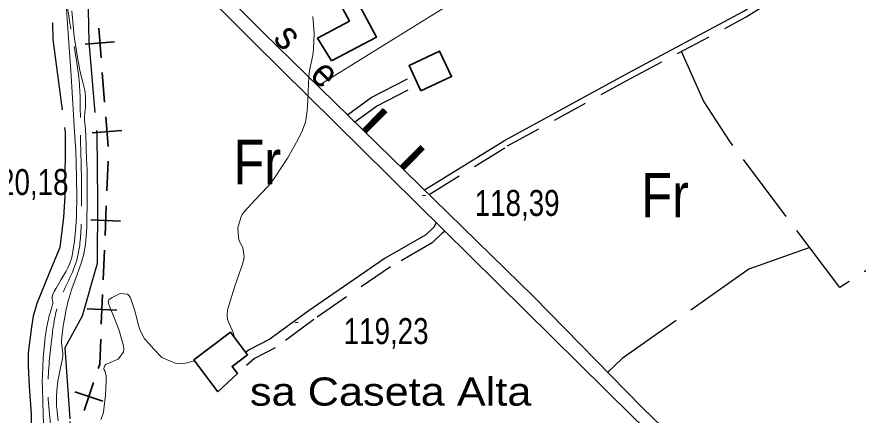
# Model space of a CAD drawing. Extents: x 483855 to 488461, y 4388206 to 4391419.
# Drawn here: x 486490 to 486774, y 4389689.8 to 4389824.2 of the extents above; entities that cross this region are included whole.
import ezdxf
from ezdxf.enums import TextEntityAlignment as Align

# ---------------------------------------------------------------- set-up
doc = ezdxf.new("R2010")
doc.units = 0
doc.header["$LTSCALE"] = 4
doc.linetypes.add('LONG_DASHED', pattern=[7.5, 6, -1.5])
doc.linetypes.add('MEDIUM_DASHED', pattern=[4.5, 3, -1.5])
for name, color, linetype, lineweight in [('15', 7, 'LONG_DASHED', 13), ('25', 7, 'LONG_DASHED', 25), ('34', 7, 'Continuous', 35), ('36', 7, 'Continuous', 25), ('38', 7, 'Continuous', 25), ('47', 7, 'Continuous', 35), ('51', 7, 'Continuous', 13), ('7', 7, 'Continuous', 13), ('9', 7, 'Continuous', 13)]:
    doc.layers.add(name, color=color, linetype=linetype, lineweight=lineweight)
doc.layers.add('31', color=7, linetype='Continuous')
doc.layers.add('5', color=7, linetype='Continuous')

msp = doc.modelspace()

# ---------------------------------------------------------------- linework, layer by layer
at = {"layer": '15'}
msp.add_spline([(486492.68, 4389960.44), (486491.95, 4389948.36), (486491.53, 4389930.05), (486491.32, 4389921.58), (486491.04, 4389911.75), (486494.3, 4389888.5), (486502.5, 4389873.13), (486507.25, 4389860.99), (486507.49, 4389847.04), (486507.43, 4389840.29), (486506.92, 4389834.21), (486508.29, 4389820.18), (486511.17, 4389801.36), (486511.49, 4389786.96), (486511.82, 4389771.21), (486511.77, 4389754.33), (486510.14, 4389741.8), (486504.02, 4389727.16), (486501.64, 4389714.03), (486500.54, 4389697.67), (486502.15, 4389678.02), (486502.16, 4389668.5), (486502.11, 4389652.44), (486501.97, 4389650.72), (486502.65, 4389644.87), (486508.82, 4389631.83), (486513.8, 4389616.98), (486525.15, 4389604.4), (486535.89, 4389591.74), (486545.82, 4389574.65), (486550.2, 4389561), (486556.75, 4389546.91), (486564.34, 4389534.32), (486574.03, 4389528.64), (486583.64, 4389523.1), (486593.92, 4389522.44), (486595.43, 4389514.79), (486597.62, 4389507.3), (486600.4, 4389500.4)], degree=3, dxfattribs=at)
at = {"layer": '25'}
for points in [[(486497.71, 4389931.68), (486497.94, 4389909.51), (486508.42, 4389877.57), (486513.1, 4389859.2), (486514.85, 4389845.55), (486514.71, 4389840.15), (486514.13, 4389826.5), (486514.3, 4389815.77), (486517.05, 4389784.57), (486517.31, 4389761.99), (486517.12, 4389740.98), (486512.05, 4389723.2), (486506.21, 4389712.54), (486507.98, 4389687.63), (486507.1, 4389672.93), (486507.66, 4389654.55), (486513.4, 4389633.26), (486522.35, 4389616.92), (486540.46, 4389597.52), (486552.42, 4389577.36), (486559.36, 4389554.57)], [(486922.38, 4389931.06), (486935.95, 4389908.14), (486948.56, 4389882.68), (486960.66, 4389857.75), (486892.81, 4389816.46), (486846.7, 4389783.53), (486767.8, 4389732.92), (486730.53, 4389782.29)], [(486501.94, 4389852.2), (486502.14, 4389816.57), (486506.4, 4389785.22), (486506.28, 4389763.7), (486505.84, 4389756.64), (486504.58, 4389746.36), (486500.92, 4389737.66), (486496.74, 4389727.52), (486495.55, 4389723.17), (486494.95, 4389719.64), (486493.92, 4389710.79), (486493.92, 4389706.51), (486494.23, 4389699.54), (486494.92, 4389690.24), (486495.01, 4389681.61)], [(486730.53, 4389782.29), (486721.8, 4389795.87), (486714.34, 4389812.5)], [(486757.69, 4389746.32), (486737.12, 4389739.05), (486694.32, 4389708.95), (486689.54, 4389704.28)]]:
    msp.add_lwpolyline(points, dxfattribs=at)
at = {"layer": '34'}
for p, q in [((486518.47, 4389810.34), (486517.67, 4389820.31)), ((486523.05, 4389815.73), (486513.09, 4389814.92)), ((486519.68, 4389795.39), (486518.87, 4389805.36)), ((486520.88, 4389780.44), (486520.08, 4389790.4)), ((486525.47, 4389785.82), (486515.5, 4389785.02)), ((486520.44, 4389765.45), (486520.85, 4389775.44)), ((486519.81, 4389750.47), (486520.23, 4389760.46)), ((486525.01, 4389755.25), (486515.02, 4389755.67)), ((486519.19, 4389735.48), (486519.6, 4389745.47)), ((486518.56, 4389720.49), (486518.98, 4389730.48)), ((486523.77, 4389725.28), (486513.77, 4389725.7)), ((486512.78, 4389691.35), (486515.95, 4389700.84)), ((486519.11, 4389694.51), (486509.62, 4389697.68))]:
    msp.add_line(p, q, dxfattribs=at)
msp.add_lwpolyline([(486517.53, 4389705.58), (486518, 4389707), (486518.35, 4389715.5)], dxfattribs=at)
at = {"layer": '36'}
for points in [[(486573.3, 4389818.73), (486553.3, 4389838.83)], [(486550.35, 4389835.26), (486570.03, 4389815.48)], [(486573.3, 4389818.73), (486664.59, 4389729.76), (486701.09, 4389692.46), (486732.39, 4389662.19), (486764.81, 4389627.09), (486793.34, 4389595.58), (486828.71, 4389556.83), (486860.49, 4389521.58), (486879.69, 4389504.55), (486889.19, 4389496.62), (486900.68, 4389489.84), (486913.43, 4389477.11), (486933.6, 4389456.96), (486953.64, 4389433.43), (486986.75, 4389395.23)], [(486570.03, 4389815.48), (486697.95, 4389689.3), (486729.21, 4389659.07), (486761.53, 4389624.08), (486790.05, 4389592.58), (486825.42, 4389553.84), (486857.35, 4389518.41), (486876.78, 4389501.18), (486886.62, 4389492.97), (486897.93, 4389486.3), (486910.28, 4389473.96), (486930.33, 4389453.93), (486950.27, 4389430.53), (486983.41, 4389392.29)]]:
    msp.add_lwpolyline(points, dxfattribs=at)
at = {"layer": '38'}
for points in [[(486627.64, 4389765.77), (486654.64, 4389782.42), (486696.21, 4389805.2), (486735.15, 4389825.93), (486757.25, 4389839.95), (486767.23, 4389839.31), (486769.19, 4389838.81)], [(486601.64, 4389791.11), (486609.69, 4389796.95), (486621.94, 4389803.22)], [(486631.53, 4389754.71), (486630.82, 4389753.25), (486628.1, 4389750.66), (486614.39, 4389742.77), (486588.33, 4389724.92), (486575.48, 4389715.42), (486568.26, 4389711.79), (486567.34, 4389710.97)]]:
    msp.add_lwpolyline(points, dxfattribs=at)
at = {"layer": '38', "linetype": 'MEDIUM_DASHED'}
for points in [[(486629.17, 4389764.28), (486655.69, 4389780.63), (486697.19, 4389803.37), (486736.2, 4389824.14), (486757.8, 4389837.83), (486766.91, 4389837.25), (486768.67, 4389836.8)], [(486604.11, 4389788.7), (486611.48, 4389794.04), (486623.49, 4389800.19)], [(486634.46, 4389751.78), (486633.63, 4389751.19), (486630.17, 4389747.9), (486616.21, 4389739.87), (486590.32, 4389722.13), (486577.28, 4389712.49), (486570.21, 4389708.94), (486567.56, 4389706.55)]]:
    msp.add_lwpolyline(points, dxfattribs=at)
at = {"layer": '47'}
for points in [[(486596.25, 4389809.28), (486611.39, 4389817.29), (486604.93, 4389829.48), (486600.07, 4389826.91), (486602.31, 4389822.67), (486591.5, 4389816.96)], [(486626.45, 4389799.19), (486622.43, 4389807.79), (486632.73, 4389812.6), (486636.75, 4389804)], [(486557.92, 4389697.74), (486549.8, 4389708.46), (486562.15, 4389717.83), (486567.92, 4389710.22), (486562.71, 4389706.28), (486564.51, 4389703.89)]]:
    msp.add_lwpolyline(points, close=True, dxfattribs=at)
at = {"layer": '51'}
msp.add_lwpolyline([(486587.29, 4389889.23), (486602.95, 4389861.48), (486638.81, 4389830.08), (486592.6, 4389801.5)], dxfattribs=at)
at = {"layer": '7'}
for p, q in [((486626.98, 4389763.9), (486627.98, 4389763.9)), ((486583.99, 4389721.05), (486584.99, 4389721.05))]:
    msp.add_line(p, q, dxfattribs=at)
at = {"layer": '9'}
msp.add_line((486563.52, 4389716.03), (486563.52, 4389716.02), dxfattribs=at)
for points in [[(486506.8, 4389827.03), (486507.05, 4389823.37)], [(486513.19, 4389786.44), (486512.99, 4389788.34), (486512.87, 4389789.53), (486512.87, 4389789.9), (486512.88, 4389790.3), (486513.02, 4389791.92), (486513.2, 4389793.74), (486513.23, 4389794.26), (486513.26, 4389794.8), (486513.26, 4389796.81), (486513.1, 4389798.82), (486513.02, 4389799.36), (486512.91, 4389799.88), (486512.39, 4389801.68), (486511.7, 4389804.18), (486511.48, 4389805.15), (486511.26, 4389806.23), (486510.37, 4389811.11), (486509.53, 4389816.85), (486509.33, 4389818.48), (486509.14, 4389820.11), (486508.6, 4389826.15)], [(486589.94, 4389824.27), (486590.42, 4389818.64), (486590.16, 4389813.37), (486590.05, 4389812.22), (486589.93, 4389811.19), (486589.37, 4389808.6), (486588.81, 4389806.06), (486588.69, 4389805.08), (486588.58, 4389803.97), (486588.33, 4389798.97), (486588.11, 4389793.85), (486588.02, 4389792.68), (486587.91, 4389791.6), (486587.45, 4389788.61), (486586.19, 4389785.35), (486585.59, 4389784.11), (486584.87, 4389782.72), (486581.39, 4389776.51), (486577.14, 4389769.98), (486575.95, 4389768.4), (486574.76, 4389766.92), (486570.39, 4389762.37), (486566.83, 4389758.55), (486566.14, 4389757.53), (486565.59, 4389756.51), (486564.65, 4389752.97), (486564.86, 4389749.85), (486565.02, 4389749.11), (486565.22, 4389748.42), (486566.35, 4389746.36), (486566.77, 4389743.27), (486566.53, 4389741.93), (486566.14, 4389740.37), (486563.47, 4389733), (486561.18, 4389725.34), (486561.03, 4389723.6), (486561.09, 4389722.03), (486563.07, 4389717.74), (486563.52, 4389716.03)], [(486507.05, 4389823.37), (486508.37, 4389804.24), (486509.66, 4389783.61), (486509.9, 4389779), (486510.08, 4389774.87), (486510.32, 4389763.95), (486510.13, 4389756.83), (486510.04, 4389755.11), (486509.94, 4389753.49), (486509.45, 4389748.51), (486508.94, 4389744.98), (486508.83, 4389744.28), (486508.73, 4389743.69), (486508.47, 4389742.54), (486508.27, 4389742.05), (486508.21, 4389741.89), (486508.14, 4389741.7), (486507.9, 4389740.92), (486507.29, 4389739.56), (486507, 4389739.01), (486506.66, 4389738.39), (486504.99, 4389735.53), (486503.31, 4389732.7), (486502.97, 4389732.09), (486502.68, 4389731.56), (486502.07, 4389730.29), (486501.91, 4389729.54), (486501.9, 4389729.35), (486501.91, 4389729.15), (486502.08, 4389728.48), (486502.19, 4389727.68), (486502.17, 4389727.41), (486502.11, 4389727.11), (486501.71, 4389725.83), (486501.13, 4389724.03), (486500.97, 4389723.4), (486500.81, 4389722.71), (486500.21, 4389719.77), (486499.65, 4389716.12), (486499.5, 4389714.99), (486499.36, 4389713.8), (486498.91, 4389709.1), (486498.66, 4389703.1), (486498.64, 4389701.1), (486498.66, 4389698.95), (486498.92, 4389689.98), (486499.25, 4389682)], [(486503.99, 4389687.92), (486503.68, 4389690.92), (486503.62, 4389691.51), (486503.56, 4389691.98), (486503.46, 4389692.82), (486503.44, 4389693.44), (486503.43, 4389693.79), (486503.43, 4389694.21), (486503.43, 4389696.36), (486503.64, 4389699.32), (486503.76, 4389700.26), (486503.92, 4389701.25), (486504.72, 4389705.25), (486505.42, 4389708.98), (486505.52, 4389709.8), (486505.57, 4389710.53), (486505.38, 4389712.4), (486505.15, 4389714.34), (486505.17, 4389715.11), (486505.22, 4389715.98), (486505.72, 4389719.98), (486506.42, 4389724.12), (486506.59, 4389725.07), (486506.76, 4389725.94), (486507.33, 4389728.42), (486508.11, 4389730.91), (486508.41, 4389731.8), (486508.76, 4389732.77), (486510.33, 4389736.98), (486511.88, 4389741.47), (486512.22, 4389742.62), (486512.51, 4389743.72), (486513.21, 4389747.33), (486513.57, 4389751.6), (486513.64, 4389753.11), (486513.7, 4389754.77), (486513.81, 4389761.96), (486513.82, 4389768.56), (486513.82, 4389769.85), (486513.81, 4389770.91), (486513.74, 4389772.78), (486513.64, 4389774.12), (486513.61, 4389774.84), (486513.58, 4389775.71), (486513.44, 4389780.11), (486513.29, 4389784.65), (486513.24, 4389785.61), (486513.19, 4389786.44)], [(486550.03, 4389708.15), (486546.97, 4389707.4), (486545.12, 4389707.29), (486543.46, 4389707.38), (486539.03, 4389709.32), (486536.18, 4389712.24), (486535.51, 4389712.95), (486534.9, 4389713.61), (486533.14, 4389715.62), (486531.78, 4389718.1), (486531.42, 4389719.07), (486531.08, 4389720.15), (486529.9, 4389725.04), (486528.46, 4389729.37), (486527.95, 4389730.1), (486527.39, 4389730.62), (486524.95, 4389730.8), (486522.68, 4389729.77), (486522.23, 4389729.53), (486521.85, 4389729.32), (486521.13, 4389728.7), (486520.96, 4389728.24), (486520.94, 4389728.12), (486520.92, 4389728.01), (486520.95, 4389727.62), (486521.55, 4389726.03), (486521.9, 4389725.17), (486522.32, 4389724.11), (486524.49, 4389718.75), (486526.08, 4389713.21), (486526.13, 4389712.04), (486526.02, 4389711.03), (486524.22, 4389708.71), (486521.85, 4389707.67), (486521.38, 4389707.46), (486520.98, 4389707.29), (486520.19, 4389706.98), (486519.92, 4389706.79), (486519.85, 4389706.7), (486519.77, 4389706.59), (486519.52, 4389706.06), (486519.42, 4389705.45), (486519.44, 4389705.29), (486519.49, 4389705.13), (486519.83, 4389704.57), (486520.14, 4389703.02), (486520.16, 4389702.23), (486520.16, 4389701.28), (486519.92, 4389696.55), (486519.43, 4389691.79), (486519.27, 4389690.82), (486519.09, 4389690), (486518.34, 4389688.31)]]:
    msp.add_lwpolyline(points, dxfattribs=at)

# ---------------------------------------------------------------- texts
at = {"layer": '31', "width": 0.85}
for p in [(486571.18, 4389767.71), (486708.86, 4389756.5)]:
    msp.add_text('Fr', height=15, dxfattribs=at).set_placement(p, align=Align.CENTER)
at = {"layer": '5'}
for s, rotation, width, p in [('s', 314.01, 0.95, (486578.31, 4389814.36)), ('e', 315.443, 0.95, (486590.89, 4389801.77)), ('l', 315.443, 1.9, (486607.33, 4389785.59)), ('l', 315.443, 1.9, (486620, 4389773.11))]:
    msp.add_text(s, height=9.49, rotation=rotation, dxfattribs=dict(at, width=width)).set_placement(p, align=Align.CENTER)
at = {"layer": '5', "width": 1.15}
msp.add_text('sa Caseta Alta', height=9.5, dxfattribs=at).set_placement((486568.72, 4389693.03))
at = {"layer": '7', "width": 0.8}
for s, p in [('120,18', (486478.85, 4389764.07)), ('118,39', (486644.59, 4389757.02)), ('119,23', (486600.37, 4389713.8))]:
    msp.add_text(s, height=8.75, dxfattribs=at).set_placement(p)

doc.saveas('drawing.dxf')
